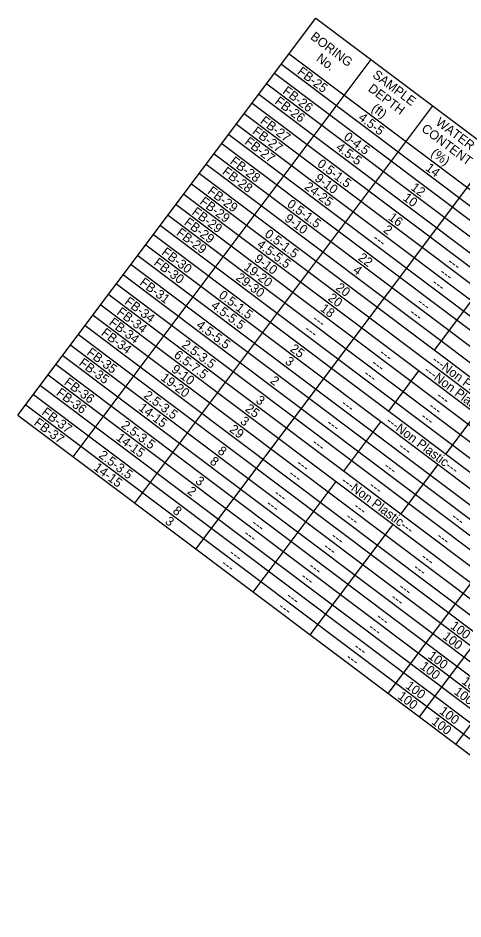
# Model space of a CAD drawing. Extents: x 627484.2 to 627517.5, y 367968.7 to 367996.9.
# Drawn here: x 627503.39 to 627506.06, y 367973.07 to 367978.47 of the extents above; entities that cross this region are included whole.
import ezdxf

# ---------------------------------------------------------------- set-up
doc = ezdxf.new("R2010")
doc.units = 0
doc.layers.add('Default', color=7, linetype='Continuous')
doc.layers.add('R_Survey Control', color=7, linetype='Continuous')

msp = doc.modelspace()

# ---------------------------------------------------------------- linework, layer by layer
at = {"layer": 'Default'}
for p, q in [((627503.3893, 367976.0855), (627505.1779, 367978.4674)), ((627505.1779, 367978.4674), (627509.6531, 367975.1069)), ((627503.7207, 367975.8367), (627505.5092, 367978.2185)), ((627505.0169, 367978.253), (627509.4921, 367974.8925)), ((627504.97, 367978.1906), (627509.4453, 367974.8301)), ((627504.9291, 367978.136), (627509.4043, 367974.7755)), ((627504.8822, 367978.0736), (627509.3575, 367974.7131)), ((627504.8354, 367978.0113), (627509.3106, 367974.6508)), ((627504.091, 367975.5586), (627505.8796, 367977.9405)), ((627504.7944, 367977.9567), (627509.2696, 367974.5962)), ((627504.7476, 367977.8943), (627509.2228, 367974.5338)), ((627504.7007, 367977.8319), (627509.176, 367974.4714)), ((627504.6539, 367977.7696), (627509.1291, 367974.4091)), ((627504.6129, 367977.715), (627509.0882, 367974.3545)), ((627504.4574, 367975.2834), (627506.246, 367977.6653)), ((627504.5661, 367977.6526), (627509.0413, 367974.2921)), ((627504.5192, 367977.5902), (627508.9945, 367974.2297)), ((627504.4783, 367977.5357), (627508.9535, 367974.1752)), ((627504.4314, 367977.4733), (627508.9067, 367974.1128)), ((627504.3846, 367977.4109), (627508.8598, 367974.0504)), ((627504.3377, 367977.3486), (627508.813, 367973.9881)), ((627505.8894, 367976.476), (627506.5334, 367977.3336)), ((627504.2909, 367977.2862), (627508.7662, 367973.9257)), ((627504.2441, 367977.2238), (627508.7193, 367973.8633)), ((627504.2031, 367977.1692), (627508.6783, 367973.8087)), ((627504.1563, 367977.1069), (627508.6315, 367973.7464)), ((627504.1094, 367977.0445), (627508.5847, 367973.684)), ((627504.0684, 367976.9899), (627508.5437, 367973.6294)), ((627504.0216, 367976.9275), (627508.4968, 367973.567)), ((627503.9806, 367976.873), (627508.4559, 367973.5125)), ((627503.9338, 367976.8106), (627508.409, 367973.4501)), ((627505.6113, 367974.417), (627507.3999, 367976.7988)), ((627503.8869, 367976.7482), (627508.3622, 367973.3877)), ((627503.8401, 367976.6858), (627508.3154, 367973.3253)), ((627503.7933, 367976.6235), (627508.2685, 367973.263)), ((627503.7523, 367976.5689), (627508.2275, 367973.2084)), ((627503.7055, 367976.5065), (627508.1807, 367973.146)), ((627505.7985, 367974.2765), (627507.4816, 367976.518)), ((627503.6586, 367976.4441), (627508.1339, 367973.0836)), ((627503.6176, 367976.3896), (627508.0929, 367973.0291)), ((627503.5708, 367976.3272), (627508.046, 367972.9667)), ((627505.6143, 367976.1096), (627505.7958, 367976.3513)), ((627506.0168, 367974.1125), (627507.6999, 367976.354)), ((627503.524, 367976.2648), (627507.9992, 367972.9043)), ((627503.483, 367976.2103), (627507.9582, 367972.8497)), ((627503.4361, 367976.1479), (627507.9114, 367972.7874)), ((627503.3893, 367976.0855), (627507.8646, 367972.725)), ((627505.9573, 367975.852), (627506.1388, 367976.0937)), ((627505.345, 367975.7509), (627505.5674, 367976.0472)), ((627505.688, 367975.4933), (627505.9105, 367975.7896)), ((627504.8005, 367975.0258), (627505.2981, 367975.6885)), ((627505.1435, 367974.7682), (627505.6412, 367975.4309))]:
    msp.add_line(p, q, dxfattribs=at)
at = {"layer": 'R_Survey Control'}
msp.add_line((627505.1779, 367978.4674), (627505.1779, 367978.4674), dxfattribs=at)

# ---------------------------------------------------------------- texts
at = {"layer": 'Default'}
for s, p in [('BORING', (627505.1397, 367978.3456)), ('No.', (627505.1753, 367978.2157)), ('FB-25', (627505.0617, 367978.1361)), ('SAMPLE', (627505.5129, 367978.1169)), ('FB-26', (627504.973, 367978.0198)), ('DEPTH', (627505.486, 367978.034)), ('FB-26', (627504.9262, 367977.9575)), ('(ft)', (627505.5058, 367977.9159)), ('4.5-5', (627505.4279, 367977.8611)), ('FB-27', (627504.8386, 367977.8404)), ('WATER', (627505.8921, 367977.8322)), ('FB-27', (627504.7917, 367977.778)), ('0-4.5', (627505.3401, 367977.7442)), ('CONTENT', (627505.8061, 367977.7936)), ('FB-27', (627504.7449, 367977.7156)), ('4.5-5', (627505.2933, 367977.6818)), ('(%)', (627505.8633, 367977.6474)), ('FB-28', (627504.6575, 367977.5984)), ('0.5-1.5', (627505.1811, 367977.5832)), ('FB-28', (627504.6107, 367977.536)), ('14', (627505.8305, 367977.5588)), ('9-10', (627505.1658, 367977.4971)), ('FB-29', (627504.5224, 367977.4194)), ('24-25', (627505.1037, 367977.4462)), ('12', (627505.7429, 367977.4417)), ('10', (627505.6959, 367977.3795)), ('FB-29', (627504.4755, 367977.357)), ('0.5-1.5', (627504.9996, 367977.3415)), ('FB-29', (627504.4287, 367977.2946)), ('9-10', (627504.9843, 367977.2554)), ('16', (627505.6081, 367977.2625)), ('FB-29', (627504.3819, 367977.2323)), ('FB-29', (627504.335, 367977.1699)), ('0.5-1.5', (627504.865, 367977.1621)), ('2', (627505.5776, 367977.1878)), ('---', (627505.5145, 367977.1377)), ('FB-30', (627504.247, 367977.0531)), ('4.5-5.5', (627504.8181, 367977.0998)), ('FB-30', (627504.2001, 367976.9907)), ('9-10', (627504.8028, 367977.0137)), ('22', (627505.4267, 367977.0207)), ('19-20', (627504.7397, 367976.9636)), ('4', (627505.3959, 367976.9463)), ('---', (627505.9629, 367976.9961)), ('29-30', (627504.6929, 367976.9012)), ('---', (627505.9161, 367976.9337)), ('FB-31', (627504.1151, 367976.8717)), ('20', (627505.2919, 367976.8415)), ('---', (627505.8693, 367976.8713)), ('0.5-1.5', (627504.5898, 367976.7957)), ('20', (627505.2451, 367976.7792)), ('FB-34', (627504.0245, 367976.7569)), ('4.5-5.5', (627504.543, 367976.7333)), ('---', (627505.7815, 367976.7544)), ('FB-34', (627503.9776, 367976.6945)), ('18', (627505.1989, 367976.7163)), ('---', (627505.7346, 367976.692)), ('FB-34', (627503.9308, 367976.6321)), ('4.5-5.5', (627504.4551, 367976.6164)), ('---', (627505.1515, 367976.6543)), ('FB-34', (627503.884, 367976.5698)), ('---', (627505.1047, 367976.5919)), ('2.5-3.5', (627504.3673, 367976.4994)), ('FB-35', (627503.7972, 367976.452)), ('25', (627505.0177, 367976.4744)), ('FB-35', (627503.7503, 367976.3897)), ('6.5-7.5', (627504.3205, 367976.4371)), ('3', (627504.9877, 367976.3994)), ('---', (627505.5531, 367976.4503)), ('9-10', (627504.3051, 367976.351)), ('---', (627505.5063, 367976.3879)), ('---Non Plastic---', (627505.8691, 367976.4081)), ('19-20', (627504.2421, 367976.3009)), ('2', (627504.8985, 367976.2834)), ('---', (627505.4595, 367976.3255)), ('---Non Plastic---', (627505.8222, 367976.3457)), ('FB-36', (627503.6616, 367976.2734)), ('FB-36', (627503.6148, 367976.211)), ('2.5-3.5', (627504.139, 367976.1954)), ('3', (627504.8121, 367976.1655)), ('---', (627505.3248, 367976.1462)), ('---', (627505.8962, 367976.1927)), ('FB-37', (627503.5272, 367976.0939)), ('14-15', (627504.1084, 367976.1208)), ('25', (627504.7484, 367976.1157)), ('---', (627505.8493, 367976.1303)), ('FB-37', (627503.4803, 367976.0315)), ('2.5-3.5', (627504.0043, 367976.016)), ('3', (627504.7184, 367976.0407)), ('---Non Plastic---', (627505.5939, 367976.0417)), ('---', (627505.8025, 367976.0679)), ('29', (627504.654, 367975.9915)), ('---', (627505.237, 367976.0293)), ('14-15', (627503.9737, 367975.9415)), ('8', (627504.5829, 367975.862)), ('---', (627505.1492, 367975.9123)), ('---', (627505.6679, 367975.8886)), ('2.5-3.5', (627503.8697, 367975.8367)), ('8', (627504.5361, 367975.7997)), ('14-15', (627503.8391, 367975.7622)), ('---', (627505.0555, 367975.7876)), ('---', (627505.58, 367975.7717)), ('---', (627505.0087, 367975.7252)), ('3', (627504.4491, 367975.6821)), ('---Non Plastic---', (627505.3246, 367975.683)), ('---', (627505.4922, 367975.6547)), ('2', (627504.4009, 367975.6207)), ('---', (627504.9208, 367975.6083)), ('---', (627504.874, 367975.5459)), ('8', (627504.3136, 367975.5034)), ('---', (627505.3985, 367975.53)), ('3', (627504.2676, 367975.4404)), ('---', (627505.3517, 367975.4676)), ('---', (627505.9855, 367975.4672)), ('---', (627504.7862, 367975.4289)), ('---', (627504.7393, 367975.3666)), ('---', (627505.2639, 367975.3507)), ('---', (627505.8976, 367975.3503)), ('---', (627505.2171, 367975.2883)), ('---', (627504.6515, 367975.2496)), ('---', (627505.804, 367975.2255)), ('---', (627504.6047, 367975.1872)), ('---', (627505.1292, 367975.1713)), ('---', (627505.7571, 367975.1632)), ('---', (627505.0824, 367975.109)), ('---', (627505.6693, 367975.0462)), ('---', (627504.9946, 367974.992)), ('---', (627505.6225, 367974.9838)), ('---', (627504.9477, 367974.9296)), ('---', (627505.5347, 367974.8669)), ('---', (627505.4878, 367974.8045)), ('100', (627505.9804, 367974.8126)), ('100', (627505.9335, 367974.7503)), ('---', (627505.4, 367974.6876)), ('100', (627505.8457, 367974.6333)), ('---', (627505.3532, 367974.6252)), ('100', (627505.7989, 367974.571)), ('100', (627505.7111, 367974.454)), ('100', (627506.0484, 367974.4811)), ('100', (627506.0016, 367974.4187)), ('100', (627505.6642, 367974.3916)), ('100', (627505.9138, 367974.3018)), ('100', (627505.8669, 367974.2394))]:
    msp.add_text(s, height=0.055, rotation=323.0968, dxfattribs=at).set_placement(p)

doc.saveas('drawing.dxf')
